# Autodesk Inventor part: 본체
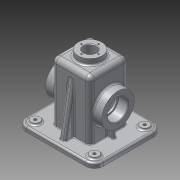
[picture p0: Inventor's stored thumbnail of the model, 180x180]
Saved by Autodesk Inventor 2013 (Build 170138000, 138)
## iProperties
Created: 2016-01
Part Number: 본체
Material: 알루미늄 6061
Document SubType Name: Modeling
Designer: Administrator
Density: 2.71 g/cm^3
Mass: 862.386 g
Surface Area: 914.264 cm^2
Volume: 318.224 cm^3
Author: Administrator
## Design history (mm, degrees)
sketch "스케치2"
  geometry: L1 (-32.5, 32.5)-(32.5, 32.5); L2 (32.5, 32.5)-(32.5, -32.5); L3 (32.5, -32.5)-(-32.5, -32.5); L4 (-32.5, -32.5)-(-32.5, 32.5); 3 further points
  constraints: 8 end point, 2 midpoint, 2 parallel, 1 horizontal, 1 horizontal alignment, 1 perpendicular, 1 vertical alignment
  dimensions: "d3" = 65 distance of L1.start L1.end; "d5" = 65 distance of L1.end L2.end
extrude "돌출1" new body sketch "스케치2" distance "d6" = 100; taper "d7" = 0 deg
sketch "스케치4"
  geometry: L1 (32.5, 100)-(32.5, 0) reference; L2 (32.5, 0)-(-32.5, 0) reference; L3 (-32.5, 0)-(-32.5, 100) reference; L4 (-32.5, 100)-(32.5, 100) reference; L5 (27.5, 95)-(27.5, 0); L6 (-27.5, 0)-(-27.5, 95); L7 (-27.5, 95)-(27.5, 95); 1 further point
  constraints: 6 end point, 2 point on line, 1 vertical, 1 other
  dimensions: "d10" = 5 distance between parallel lines of L3 L6; "d11" = 5 distance between parallel lines of L1 L5
extrude "돌출2" cut sketch "스케치4" stored distance "d12" = 55; taper "d13" = 0 deg
sketch "스케치5"
  geometry: C1 r 20 at (0, 0); 1 further point
  constraints: 1 centre point, 1 coincident
  dimensions: "d14" = 40 diameter of C1
extrude "돌출3" join sketch "스케치5" distance "d15" = 10; taper "d16" = 0 deg
hole "구멍1" diameter "d19" = 21; stored, may be unused: countersink angle "d23" = 90 deg, drill point angle "d25" = 0 deg; dims "d17" = 10, "d18" = 10, "d20" = 6, "d21" = 4, "d22" = 2, "d24" = 8
sketch "스케치7"
  geometry: L1 (-27.5, -27.5)-(27.5, -27.5) reference; L2 (27.5, -27.5)-(27.5, 27.5) reference; L3 (27.5, 27.5)-(-27.5, 27.5) reference; L4 (-27.5, 27.5)-(-27.5, -27.5) reference; L5 (32.5, 32.5)-(32.5, -32.5) reference; L6 (32.5, -32.5)-(-32.5, -32.5) reference; L7 (-32.5, -32.5)-(-32.5, 32.5) reference; L8 (-32.5, 32.5)-(32.5, 32.5) reference; L9 (-65, -57.5)-(65, -57.5); L10 (65, -57.5)-(65, 57.5); L11 (65, 57.5)-(-65, 57.5); L12 (-65, 57.5)-(-65, -57.5); 3 further points
  constraints: 8 end point, 2 midpoint, 2 parallel, 1 horizontal, 1 horizontal alignment, 1 perpendicular, 1 vertical alignment
  dimensions: "d30" = 130 distance of L9.start L9.end; "d32" = 115 distance of L9.end L10.end
extrude "돌출5" join sketch "스케치7" distance "d33" = 8; taper "d34" = 0 deg
sketch "스케치9"
  geometry: L1 (-27.5, -27.5)-(-27.5, 27.5) reference; L2 (-27.5, 27.5)-(27.5, 27.5) reference; L3 (27.5, 27.5)-(27.5, -27.5) reference; L4 (27.5, -27.5)-(-27.5, -27.5) reference; L5 (-60, -52.5)-(60, -52.5); L6 (60, -52.5)-(60, 52.5); L7 (60, 52.5)-(-60, 52.5); L8 (-60, 52.5)-(-60, -52.5); 3 further points
  constraints: 8 end point, 2 midpoint, 2 parallel, 1 horizontal, 1 horizontal alignment, 1 perpendicular, 1 vertical alignment
  dimensions: "d35" = 120 distance of L6.end L7.end; "d37" = 105 distance of L7.end L5.start
extrude "돌출6" join sketch "스케치9" distance "d38" = 2; taper "d39" = 0 deg
fillet "모깎기3" dims "d45" = 15
sketch "스케치13"
  geometry: C1 r 7.5 at (-50, 42.5); C2 r 7.5 at (50, 42.5); C3 r 7.5 at (-50, -42.5); C4 r 7.5 at (50, -42.5); A1 r 15 centre (-50, 42.5) between (-50, 57.5) and (-65, 42.5) reference; A2 r 15 centre (-50, -42.5) between (-65, -42.5) and (-50, -57.5) reference; A3 r 15 centre (50, -42.5) between (50, -57.5) and (65, -42.5) reference; A4 r 15 centre (50, 42.5) between (65, 42.5) and (50, 57.5) reference; 1 further point
  constraints: 4 centre point, 4 coincident
  dimensions: "d46" = 15 diameter of C1; "d47" = 15 diameter of C2; "d48" = 15 diameter of C3; "d49" = 15 diameter of C4
extrude "돌출7" join sketch "스케치13" distance "d50" = 3; taper "d51" = 0 deg
fillet "모깎기4" dims "d52" = 10
hole "구멍2" diameter "d55" = 5; stored, may be unused: countersink angle "d59" = 90 deg, drill point angle "d61" = 0 deg; dims "d53" = 10, "d54" = 10, "d56" = 6, "d57" = 4, "d58" = 2, "d60" = 8
hole "구멍3" diameter "d64" = 5; stored, may be unused: countersink angle "d68" = 90 deg, drill point angle "d70" = 0 deg; dims "d62" = 10, "d63" = 10, "d65" = 6, "d66" = 4, "d67" = 2, "d69" = 8
fillet "모깎기5" dims "d71" = 8
fillet "모깎기6" dims "d72" = 8
node "작업 평면1"
sketch "스케치14"
  geometry: L1 (10, 67)-(10, -18) reference; C1 r 27.5 at (-45, 24.5); 2 further points
  constraints: 1 centre point, 1 horizontal alignment, 1 midpoint
  dimensions: "d74" = 55 diameter of C1; "d75" = 55 distance from line of L1 C1.centre
extrude "돌출8" join sketch "스케치14" stored distance "d76" = 3; taper "d77" = 0 deg
hole "구멍4" diameter "d80" = 30; stored, may be unused: countersink angle "d84" = 90 deg, drill point angle "d86" = 0 deg; dims "d78" = 10, "d79" = 10, "d81" = 6, "d82" = 35, "d83" = 17, "d85" = 8
sketch "스케치15"
  geometry: C1 r 17.5 at (0, 0) reference; 2 further points
  constraints: 1 horizontal alignment
  dimensions: "d87" = 21 distance of C1.centre point (-21, 0)
hole "구멍5" sketch "스케치15" at (-21, 0) diameter "d88" = 3.242; stored, may be unused: countersink angle "d92" = 90 deg, drill point angle "d94" = 118 deg; dims "d89" = 8, "d90" = 35, "d91" = 17, "d93" = 10
sketch "스케치17"
  geometry: C1 r 10.5 at (0, 0) reference; 1 further point
  constraints: 1 horizontal alignment
  dimensions: "d98" = 14.5 distance of C1.centre point (-14.5, 0)
hole "구멍6" sketch "스케치17" at (-14.5, 0) diameter "d99" = 2.459; stored, may be unused: countersink angle "d103" = 90 deg, drill point angle "d105" = 118 deg; dims "d100" = 7, "d101" = 35, "d102" = 17, "d104" = 9
sketch "스케치19"
  geometry: L1 (47.5, 17.5)-(32.5, 17.5) reference; L2 (32.5, 17.5)-(32.5, 0) reference; L3 (32.5, 0)-(65, 0) reference; L4 (65, 0)-(65, -8) reference; L5 (65, -8)-(60, -8) reference; L6 (60, -8)-(60, -10) reference; L7 (60, -10)-(27.5, -10) reference; L8 (27.5, -10)-(27.5, 30) reference; L9 (27.5, 30)-(30.5, 30) reference; L10 (30.5, 30)-(30.5, 27.5) reference; L11 (30.5, 27.5)-(47.5, 27.5) reference; L12 (47.5, 27.5)-(47.5, 25.621) reference; L13 (47.5, 25.621)-(37.5, 25.621) reference; L14 (37.5, 25.621)-(36.526, 24) reference; L15 (36.526, 24)-(37.5, 22.379) reference; L16 (37.5, 22.379)-(47.5, 22.379) reference; L17 (47.5, 22.379)-(47.5, 17.5) reference; L18 (-60, -10)-(-60, -8) reference; L19 (-60, -8)-(-65, -8) reference; L20 (-65, -8)-(-65, 0) reference; L21 (-65, 0)-(-32.5, 0) reference; L22 (-32.5, 0)-(-32.5, 17.5) reference; L23 (-32.5, 17.5)-(-47.5, 17.5) reference; L24 (-47.5, 17.5)-(-47.5, 22.379) reference; L25 (-47.5, 22.379)-(-37.5, 22.379) reference; L26 (-37.5, 22.379)-(-36.526, 24) reference; L27 (-36.526, 24)-(-37.5, 25.621) reference; L28 (-37.5, 25.621)-(-47.5, 25.621) reference; L29 (-47.5, 25.621)-(-47.5, 27.5) reference; L30 (-47.5, 27.5)-(-30.5, 27.5) reference; L31 (-30.5, 27.5)-(-30.5, 30) reference; L32 (-30.5, 30)-(-27.5, 30) reference; L33 (-27.5, 30)-(-27.5, -10) reference; L34 (-27.5, -10)-(-60, -10) reference; L35 (-10.5, 110)-(-10.5, 95) reference; L36 (-10.5, 95)-(-27.5, 95) reference; L37 (-27.5, 95)-(-27.5, 60) reference; L38 (-27.5, 60)-(-30.5, 60) reference; L39 (-30.5, 60)-(-30.5, 62.5) reference; L40 (-30.5, 62.5)-(-47.5, 62.5) reference; L41 (-47.5, 62.5)-(-47.5, 64.379) reference; L42 (-47.5, 64.379)-(-37.5, 64.379) reference; L43 (-37.5, 64.379)-(-36.526, 66) reference; L44 (-36.526, 66)-(-37.5, 67.621) reference; L45 (-37.5, 67.621)-(-47.5, 67.621) reference; L46 (-47.5, 67.621)-(-47.5, 72.5) reference; L47 (-47.5, 72.5)-(-32.5, 72.5) reference; L48 (-32.5, 72.5)-(-32.5, 92) reference; L49 (-24.5, 100)-(-20, 100) reference; L50 (-20, 100)-(-20, 110) reference; L51 (-20, 110)-(-15.73, 110) reference; L52 (-15.73, 110)-(-15.73, 101) reference; L53 (-15.73, 101)-(-14.5, 100.261) reference; L54 (-14.5, 100.261)-(-13.271, 101) reference; L55 (-13.271, 101)-(-13.271, 110) reference; L56 (-13.271, 110)-(-10.5, 110) reference; L57 (10.5, 95)-(10.5, 110) reference; L58 (10.5, 110)-(13.271, 110) reference; L59 (13.271, 110)-(13.271, 101) reference; L60 (13.271, 101)-(14.5, 100.261) reference; L61 (14.5, 100.261)-(15.73, 101) reference; L62 (15.73, 101)-(15.73, 110) reference; L63 (15.73, 110)-(20, 110) reference; L64 (20, 110)-(20, 100) reference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; A1 r 8 centre (-24.5, 92) between (-24.5, 100) and (-32.5, 92) reference; A2 r 8 centre (24.5, 92) between (32.5, 92) and (24.5, 100) reference; 1 further point
  constraints: 2 end point, 2 point on line, 1 vertical
  dimensions: "d111" = 15 distance between parallel lines of L79 L8
feature "리브1" sketch "스케치19" dims "d112" = 1, "d113" = 6, "d114" = 0, "d115" = 0, "d116" = 1, "d117" = 1
sketch "스케치20"
  geometry: L1 (52.5, -10)-(27.5, -10) reference; L2 (27.5, -10)-(27.5, 95) reference; L3 (27.5, 95)-(10.5, 95) reference; L4 (10.5, 95)-(10.5, 110) reference; L5 (10.5, 110)-(13.271, 110) reference; L6 (13.271, 110)-(13.271, 101) reference; L7 (13.271, 101)-(14.5, 100.261) reference; L8 (14.5, 100.261)-(15.73, 101) reference; L9 (15.73, 101)-(15.73, 110) reference; L10 (15.73, 110)-(20, 110) reference; L11 (20, 110)-(20, 100) reference; L12 (20, 100)-(24.5, 100) reference; L13 (32.5, 92)-(32.5, 0) reference; L14 (32.5, 0)-(57.5, 0) reference; L15 (57.5, 0)-(57.5, -8) reference; L16 (57.5, -8)-(52.5, -8) reference; L17 (52.5, -8)-(52.5, -10) reference; L18 (-27.5, -10)-(-52.5, -10) reference; L19 (-52.5, -10)-(-52.5, -8) reference; L20 (-52.5, -8)-(-57.5, -8) reference; L21 (-57.5, -8)-(-57.5, 0) reference; L22 (-57.5, 0)-(-32.5, 0) reference; L23 (-32.5, 0)-(-32.5, 92) reference; L24 (-24.5, 100)-(-20, 100) reference; L25 (-20, 100)-(-20, 110) reference; L26 (-20, 110)-(-15.73, 110) reference; L27 (-15.73, 110)-(-15.73, 101) reference; L28 (-15.73, 101)-(-14.5, 100.261) reference; L29 (-14.5, 100.261)-(-13.271, 101) reference; L30 (-13.271, 101)-(-13.271, 110) reference; L31 (-13.271, 110)-(-10.5, 110) reference; L32 (-10.5, 110)-(-10.5, 95) reference; L33 (-10.5, 95)-(-27.5, 95) reference; L34 (-27.5, 95)-(-27.5, -10) reference; L35 (32.5, 85.069)-(47.5, 0); A1 r 8 centre (24.5, 92) between (32.5, 92) and (24.5, 100) reference; A2 r 8 centre (-24.5, 92) between (-24.5, 100) and (-32.5, 92) reference; 1 further point
  constraints: 2 end point, 2 point on line
  dimensions: "d118" = 10 deg angle of L15 L35; "d119" = 10 distance from line of L15 L35.end
feature "리브2" sketch "스케치20" dims "d120" = 1, "d121" = 10, "d122" = 0, "d123" = 0, "d124" = 1, "d125" = 1
fillet "모깎기7" dims "d126" = 0.3
fillet "모깎기8" dims "d127" = 3
fillet "모깎기9" dims "d128" = 3
fillet "모깎기10" dims "d129" = 3
fillet "모깎기11" dims "d130" = 3
fillet "모깎기12" dims "d131" = 3
fillet "모깎기13" dims "d132" = 1
fillet "모깎기14" dims "d133" = 3
fillet "모깎기15" dims "d134" = 3
sketch "스케치22"
  geometry: L1 (18, 4.5)-(18, 44.5) reference; L2 (0, 57)-(-91, 57) reference; 2 further points
  constraints: 1 other
  dimensions: "d135" = 27 distance from line of L1 point (-9, 24.5); "d136" = 32.5 distance from line of L2 point (-9, 24.5)
feature "엠보싱1" sketch "스케치22" dims "d137" = 0.5, "d138" = 0
chamfer "모따기1" distance "d139" = 1; stored, may be unused: second distance "d140" = 2, angle "d141" = 45 deg
node "솔리드1"
mirror "대칭1"
pattern_circular "원형 패턴1" dims angle "d96" = 360 deg
mirror "대칭3"
pattern_circular "원형 패턴2" dims angle "d107" = 360 deg
mirror "대칭4"
mirror "대칭5"
node "절단 모서리 투영2"
node "절단 모서리 투영3"
node "절단 모서리 투영4"
node "절단 모서리 투영5"
other parameters: "d73" = 15, "d109" = 15
